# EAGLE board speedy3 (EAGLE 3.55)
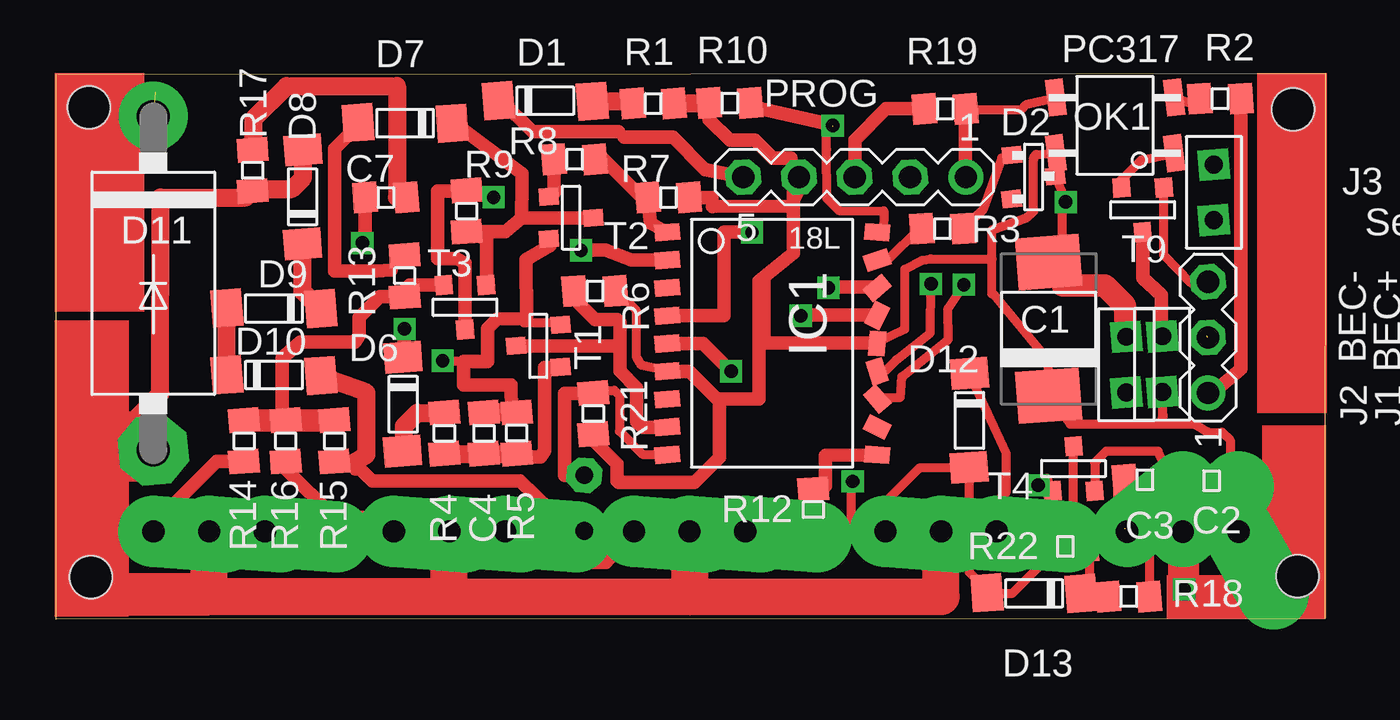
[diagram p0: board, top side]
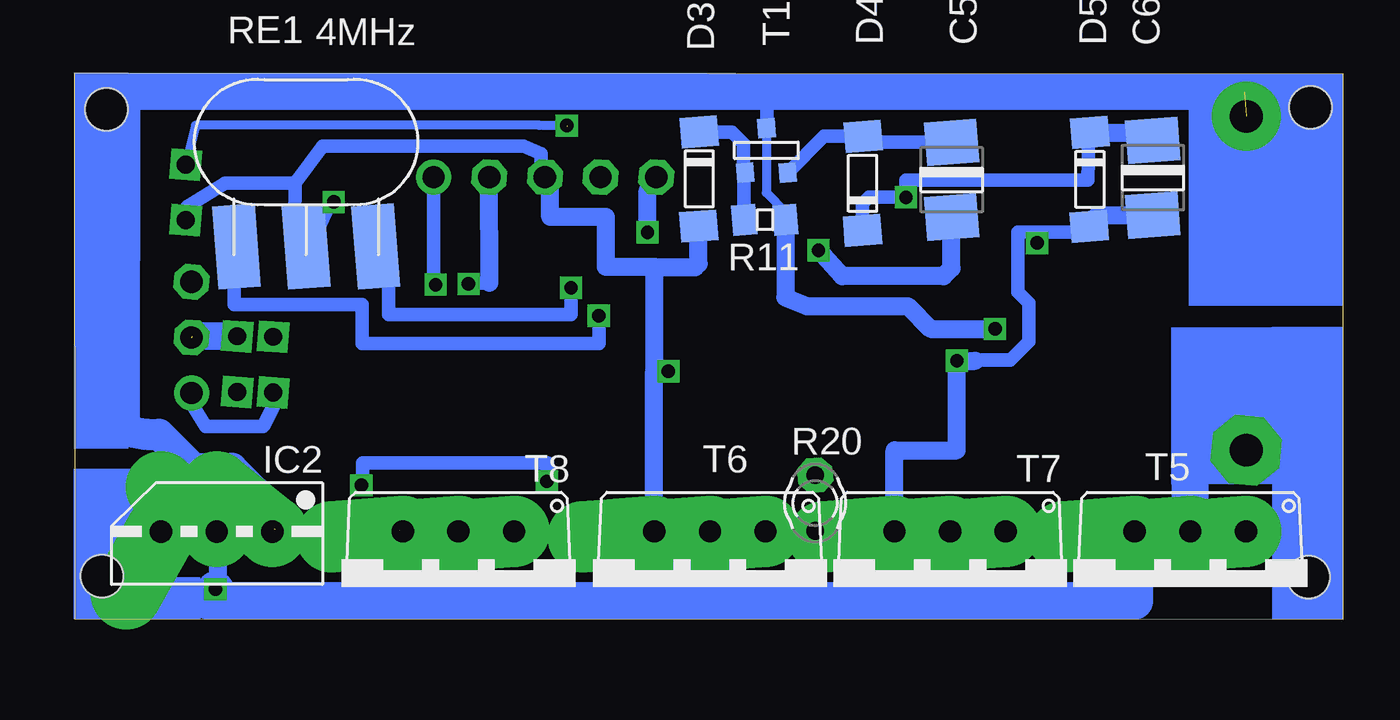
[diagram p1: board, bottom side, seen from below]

Size 57.92 x 24.93 mm. Coordinates in mm from the lower left corner, seen from the top.
Outline: 0,24.89 57.92,24.93 57.9,0.02 0,0 0,24.89
Copper layers used: Top, Bottom
Holes 1.93 mm at 1.5,23.37 1.58,1.92 56.64,1.97 56.45,23.28

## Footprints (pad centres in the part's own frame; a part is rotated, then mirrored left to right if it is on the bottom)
43 = smd 2.388 x 2.896 rotated 4.4:  3.048,0 | smd 2.388 x 2.896 rotated 4.3:  -3.048,0
05 = smd 1.092 x 1.397 rotated 4.4:  0.94,0 | smd 1.092 x 1.397 rotated 4.3:  -0.94,0
28 = smd 2.007 x 2.388 rotated 4.4:  1.702,0 | smd 2.007 x 2.388 rotated 4.3:  -1.702,0
D-80 = smd 1.397 x 1.702 rotated 4.4:  -2.388,0 | smd 1.397 x 1.702 rotated 4.3:  1.905,-0.025
T-23 = smd 0.787 x 0.889 rotated 6.7:  -1.24,-0.669 | smd 0.787 x 0.889 rotated 5.7:  0.754,-0.688 | smd 0.787 x 0.889 rotated 6.6:  -0.197,-2.662
201-15 = drill 1.499 pad 3.15 round:  -7.62,0 | drill 1.499 pad 3.15 octagon:  7.62,0
-18L = smd 0.762 x 1.143 rotated 4.3:  -5.08,-5.131;  5.08,4.445 | smd 0.762 x 1.143 rotated 4.4:  -3.81,-5.131 | smd 0.762 x 1.143 rotated 4.5:  -2.54,-5.131 | smd 0.762 x 1.143 rotated 4.6:  -1.27,-5.131 | smd 0.762 x 1.143 rotated 4.7:  0,-5.131;  1.27,-5.131 | smd 0.762 x 1.143 rotated 4.8:  2.54,-5.131 | smd 0.762 x 1.143 rotated 4.9:  3.81,-5.131 | smd 0.762 x 1.143 rotated 5:  5.08,-5.131 | smd 0.762 x 1.143 rotated 26.8:  3.81,4.445 | smd 0.762 x 1.143 rotated 49.3:  2.54,4.445 | smd 0.762 x 1.143 rotated 71.8:  1.27,4.445 | smd 0.762 x 1.143 rotated 94.3:  0,4.445 | smd 0.762 x 1.143 rotated 116.8:  -1.27,4.445 | smd 0.762 x 1.143 rotated 139.3:  -2.54,4.445 | smd 0.762 x 1.143 rotated 161.8:  -3.81,4.445 | smd 0.762 x 1.143 rotated 184.3:  -5.08,4.445
MXXS = drill 1.016 pad 3.251 offset:  -2.54,-2.54;  0,-2.54;  2.54,-2.54
N2 = drill 0.813 pad 1.397 square:  -1.27,0;  1.27,0
D4 = smd 0.813 x 1.676 rotated 97:  -1.27,-2.54;  1.27,-2.54;  1.27,2.857;  -1.27,2.857
05-1 = drill 1.016 pad 1.6 round:  -5.08,0 | drill 1.016 pad 1.6 octagon:  -2.54,0;  0,0;  2.54,0;  5.08,0
40 = drill 0.813 pad 1.6 octagon:  -1.27,0;  1.27,0
SONAT = smd 1.93 x 3.81 rotated 4.5:  3.175,-4.445 | smd 1.93 x 3.81 rotated 4.3:  -3.175,-4.445 | smd 1.93 x 3.81 rotated 4.4:  0,-4.445
03-1 = drill 1.016 pad 1.6 round:  -2.54,0 | drill 1.016 pad 1.6 octagon:  0,0;  2.54,0
T-23' = smd 0.787 x 0.889 rotated 4.4:  0.991,1.016 | smd 0.787 x 0.889 rotated 4.3:  -0.94,1.016 | smd 0.787 x 0.889 rotated 4.5:  0.025,-1.016
220V = drill 1.016 pad 3.251 offset:  -2.54,-2.54;  0,-2.54;  2.54,-2.54

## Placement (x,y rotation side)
C1  47u/10  [43]  45.29,13.25 90 top
C2  100n  [05]  52.72,6.33 0 top
C3  100n  [05]  49.69,6.37 180 top
C4  47n  [05]  19.52,8.5 90 top
C5  2æ2/25  [28]  17.88,20.07 270 bottom
C6  3u3/20  [28]  8.7,20.16 270 bottom
C7  22n  [05]  15.04,19.26 0 top
D1  LL4148  [D-80]  22.56,23.67 0 top
D2  LED-SMD  [T-23]  42.93,20.43 90 top
D3  15V  [D-80]  29.39,19.86 270 bottom
D4  LL4148  [D-80]  21.94,20.14 90 bottom
D5  ZDIO-15V  [D-80]  11.57,19.84 270 bottom
D6  ZDIO-5V6  [D-80]  15.83,9.58 270 top
D7  LL4148  [D-80]  15.68,22.64 180 top
D8  LL4148  [D-80]  11.24,19.52 90 top
D9  ZDIO-22V  [D-80]  9.7,14.18 180 top
D10  ZDIO-22V  [D-80]  10.18,11.15 0 top
D11  SB550  [201-15]  4.43,15.34 270 top
D12  ZD15  [D-80]  41.68,8.84 270 top
D13  LL4148  [D-80]  44.38,1.19 180 top
IC1  16F84SO  [-18L]  33.02,12.59 270 top
IC2  LM2940CT  [MXXS]  51.41,1.47 180 bottom
J1  BEC+  [N2]  50.47,11.65 90 top
J2  BEC-  [N2]  48.83,11.63 270 top
J3  Setup  [N2]  52.83,19.49 270 top
OK1  PC317  [D4]  48.47,22.55 90 top
PROG  MA05-1  [05-1]  36.43,20.19 180 top
R1  1k  [05]  27.25,23.54 180 top
R2  120  [05]  53.12,23.76 180 top
R3  470  [05]  40.45,17.83 180 top
R4  1k  [05]  17.71,8.5 90 top
R5  1k  [05]  21.02,8.5 270 top
R6  47k  [05]  24.58,14.99 0 top
R7  1k  [05]  27.94,19.26 0 top
R8  4k7  [05]  23.65,21 0 top
R9  47k  [05]  18.73,18.64 90 top
R10  1k  [05]  30.73,23.57 0 top
R11  10k  [05]  26.4,18.24 0 bottom
R12  47k  [05]  34.55,5 270 top
R13  470  [05]  15.91,15.67 270 top
R14  220  [05]  8.57,8.14 90 top
R15  220  [05]  12.7,8.14 90 top
R16  220  [05]  10.48,8.14 90 top
R17  47  [05]  8.97,20.49 270 top
R18  10k  [05]  48.94,1.04 0 top
R19  4k7  [05]  40.56,23.3 0 top
R20  NTC 10k  [40]  24.1,5.31 90 bottom
R21  4k7  [05]  24.51,9.39 270 top
R22  82k  [05]  46.06,3.33 180 top
RE1  4MHz  [SONAT]  47.33,21.47 0 bottom
REC  MA03-1  [03-1]  52.56,12.87 90 top
T1  BC817  [T-23']  22,12.51 270 top
T2  BC817  [T-23']  23.49,18.3 90 top
T3  BC817  [T-23']  18.63,14.24 0 top
T4  BC817  [T-23']  46.45,6.88 180 top
T5  IRF3205  [220V]  6.98,1.48 180 bottom
T6  IRF3205  [220V]  28.91,1.48 180 bottom
T7  IRF3205  [220V]  17.95,1.48 180 bottom
T8  IRF9540 o..  [220V]  40.38,1.48 180 bottom
T9  BC817  [T-23']  49.55,18.69 0 top
T10  BC817  [T-23']  26.3,21.41 180 bottom

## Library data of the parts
C1 C5 C6 D1 D3-D10 D12 D13 R11 R14 R19 R21 R22 T9 T10 = SMD
C2-C4 C7 R2 R15-R17 = DEMO
D2 J1-J3 OK1 = d-part
D11 = DIODE
IC1 = PIC
IC2 = V-REG
PROG REC = CON-LSTB
R1 R3-R10 R12 R13 R18 = DISCRETE
R20 = ptc-ntc
RE1 = hans
T1-T4 = NPN
T5-T8 = FET

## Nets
+15V: C6. D4. D5. R9. T3.
AKKU+: C3. D6. D11. D12. IC2. R11. R18. T8. T10.
GND: C1. C2. C3. C4. C6. C7. D2. D3. D5. IC1. IC2. J2. J3. PROG. R5. R19. R20. RE1. T1. T2. T4. T5. T6. T7.
N$1: IC1. RE1.
N$3: IC1. PROG.
N$4: C5. IC1.
N$5: REC. T9.
N$6: IC1. R3.
N$8: D6. R4.
N$9: D2. R3.
N$10: R8. T2.
N$11: C4. R4. R5. T1.
N$12: IC1. R6. T1.
N$13: IC1. R7. R8.
N$14: R13. R14. R15. R16. T3.
N$15: R12. T4.
N$16: IC1. R12.
N$18: D7. R9. T2. T3.
N$19: IC1. J3. R10.
N$20: D8. D11. R17. T5. T6. T7. T8.
N$21: D7. R13.
N$22: IC1. RE1.
N$23: J1. REC. T9.
N$24: D10. R15. T6.
N$25: OK1. T9.
N$26: D1. IC1. PROG.
N$27: C5. D4. T10.
N$28: D8. D9.
N$29: IC1. OK1. PROG. R19.
N$30: D3. R11. T10.
N$31: OK1. R2.
N$32: R16. T7.
N$33: IC1. R20. R21.
N$34: D1. R1.
N$35: D9. D10.
N$37: C7. R17.
N$38: R14. T5.
N$39: J2. R2. REC.
N$41: D13. R18. R22. T4.
N$43: D12. D13. R22. T8.
VCC: C1. C2. IC1. IC2. J1. OK1. PROG. R1. R6. R7. R10. R21.

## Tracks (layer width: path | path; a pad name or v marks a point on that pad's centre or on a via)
+15V  (via drill 0.61 pad 1.02)
  Top 0.406: 18.73,19.58 18.73,19.26 18.66,19.54 18.67,19.54 18.69,19.52 | 17.42,19.45 17.41,19.46 17.41,19.54 | v19.96,19.27 18.92,19.28 18.68,19.52 18.69,19.52 | 18.69,19.52 18.7,19.51
  Top 0.61: T3. 18.66,16.27 18.27,16.47 17.41,16.47 17.41,19.54 18.66,19.54
  Bottom 0.406: C6. 8.81,22.01 8.82,22 9.05,22.23 | 11.57,22.23 11.65,22.23 11.72,22.3 | v19.96,19.27 v19.96,19.28 19.93,19.31 19.97,19.35
  Bottom 0.61: 11.65,22.23 11.65,20.95 11.66,20.06 19.97,20.06 19.97,19.35 | v19.96,19.28 21.64,19.28 21.94,18.98 21.94,17.84 21.97,17.81 21.94,17.78 21.94,17.75
  Bottom 0.813: 11.65,22.23 9.05,22.23
AKKU+  (via drill 0.61 pad 1.02)  (3 unrouted)
  Top 0.406: 43.36,7.57 43.36,5.8 43.06,5.5 43.06,4.07 43.07,4.07 T8. | 43.36,7.57 | 43.36,7.57 41.68,11.23 | 48.83,3.85 48.83,3.95 48.84,3.96 49.88,2.92 49.88,1.04 | 48.82,3.96 48.9,4.04 | v48.78,3.96 48.82,3.96 | v48.77,3.95 48.81,3.95 48.82,3.96
  Top 0.61: v15.9,13.26 15.87,13.26 15.87,11.97 15.83,11.97 | 48.88,3.99 48.75,4.12 | 48.88,3.99 48.77,3.99 | 48.87,3.95 48.84,3.92 | 48.87,3.95 48.87,4.01 | 48.88,3.96 48.88,3.99 | 48.88,3.96 48.87,3.95 | 48.88,3.96 48.84,3.96 v48.78,3.96 v48.77,3.95 48.84,3.95
  Top 1.016: 48.75,4.12 48.75,6.37
  Bottom 0.406: 27.87,24.09 27.91,24.15 28.04,24.13 | 26.24,22.59 T10. 26.33,19.47 25.46,18.6 25.46,18.24 25.46,18.14 25.41,18.09 25.45,18.05 25.41,17.8 25.3,18.1 25.3,18.16 | 25.3,18.16 25.41,18.27 | 25.3,18.16 25.46,17.87 | 48.9,4.15 48.9,3.96 48.9,3.95 v48.77,3.95 | 48.85,4.06 48.79,4.12 48.75,4.12 | 43.06,4.06 48.85,4.06 | 48.85,4.06 48.93,3.98
  Bottom 0.61: 26.24,22.59 26.29,22.59 26.29,24.2 27.91,24.2 | 27.91,24.2 27.91,24.15 27.87,24.09 | 27.91,24.2 27.91,24.24
  Bottom 0.813: v15.9,13.26 18.84,13.26 19.88,14.3 24.48,14.3 25.46,14.7 25.46,17.87
  Bottom 1.422: 55.62,24.09 55.62,8.62 54.6,8.45 54.04,8.45 52.49,6.9 50.72,6.9 48.75,4.93 48.75,4.01 48.8,3.96 48.8,3.88 | 48.8,3.88 48.83,3.85 | v48.78,3.96 48.78,3.9 48.8,3.88
  Bottom 1.676: 4.52,24.06 27.87,24.09 55.62,24.09 55.64,24.09
GND  (via drill 0.61 pad 1.02)
  Top 0.406: 22.54,17.35 22.53,17.37 22.48,17.37 | v17.63,11.8 18.61,11.79 | 27.81,12.62 27.84,12.62 27.87,12.65 27.93,12.59 | 20.79,9.49 21.19,9.4 | 21.19,9.4 21.09,9.3 21.19,9.3 21.19,9.4 | 19.52,9.44 19.52,9.53 19.54,9.55 19.65,9.44 | 21.19,9.4 21.19,9.44 R5. | v13.97,17.18 14.1,17.69 | 45.91,15.96 45.29,16.3 45.89,15.27 45.9,18.52 v46.07,19.05 46.03,18.91 | J3. 52.82,18.37 52.86,18.33 | 21.46,13.73 21.46,13.67 21.34,13.55 21.35,13.54 23.01,13.54 23.02,13.54 | 18.6,10.7 18.61,10.69 | 18.6,11.78 18.61,11.77 18.61,11.79 | 23.02,13.54 23.05,13.58 | 23.02,13.54 23.02,13.45 | 18.61,11.79 18.61,11.69 18.62,11.68 18.72,11.78 | D2. 45.99,19.34 46,19.02 46.03,18.91 | 46.03,18.91 46.06,18.88 | 47.39,5.87 47.39,7.15 47.9,7.67 50.28,7.67 50.71,6.84 50.71,6.49 50.63,6.57 C3.
  Top 0.61: v30.8,11.32 29.53,12.59 27.93,12.59 | 22.54,17.35 22.54,17.07 21.44,16.43 21.46,13.73 20.13,13.72 19.68,13.27 19.68,11.78 18.72,11.78 | 20.79,9.49 20.77,10.69 18.61,10.69 | 14.1,17.69 C7. | R19. 37.87,23.3 36.45,21.88 v36.45,20.18 | 18.6,11.78 18.6,10.7 | 45.29,16.3 45.92,15.27 45.91,15.27 45.94,15.24
  Top 0.813: R5. 19.65,9.44
  Top 1.016: 48.83,12.9 48.77,14.32 47.85,15.24 45.94,15.24 | 51.37,6.36 51.38,6.46 51.41,4.01 | 51.37,6.36 C2. | 51.37,6.36 51.23,6.36 51.26,6.52 51.24,6.5 C3.
  Top 1.422: v51.47,1.37 51.41,4.01
  Bottom 0.406: T7. 20.95,2.43 20.64,0.84 20.5,1.16 | 31.44,3.7 T6. | 36.43,20.19 36.51,20.21 36.2,20.21 | v30.8,11.32 31.43,11.32 | 11.21,18.46 11.67,18 11.61,17.93 D5. 11.59,17.92 11.83,17.68 11.83,17.67 11.85,17.66 11.88,17.68 | 47.91,16.45 47.91,16.35 | 47.91,16.45 47.87,16.45 47.97,16.35 47.97,16.25 47.14,16.84 v46.07,19.05 | RE1. 47.91,16.93 47.91,16.45 | 14.32,17.72 14.28,17.68 | 29.57,16.08 29.41,16.23 | 31.59,15.97 31.48,16.08 31.48,16.07 | 31.48,16.07 31.51,16.04 | 31.43,16.08 31.46,16.08 31.48,16.07 | v13.97,17.18 13.96,17.58 13.97,17.58 13.98,17.65 14.2,17.43 14.32,17.72 | 14.32,17.72 14.31,17.73 | 14.84,17.68 14.35,17.68 14.32,17.72 | 52.75,18.83 52.84,18.66 | 51.34,1.26 51.97,1.07 51.99,1.09 v51.47,1.37 | 36.43,20.19 36.43,20.23 36.62,20.42 | 36.36,20.18 36.26,20.08 | 36.43,20.19 36.37,20.19 36.36,20.18 | 17.53,11.83 16.67,11.94 | 17.53,11.83 17.54,11.83 | 16.81,11.8 17.53,11.83 | 20.43,7.67 20.39,7.63 | 20.43,7.67 20.44,7.67 | 20.48,7.72 20.43,7.67 | 36.53,20.19 36.52,20.18 v36.45,20.18 36.36,20.18 | 36.43,20.19 36.53,20.19 | 36.53,20.19 36.55,20.21
  Bottom 0.61: 47.83,19.92 46.57,21.6 37.4,21.6 36.62,21.25 36.62,20.42 | 47.83,19.92 47.87,16.45 | 17.54,11.83 16.19,11.84 15.19,11.84 14.35,12.68 14.35,14.45 14.84,14.94 14.84,17.68 11.88,17.68 | 52.84,18.66 J3. | 47.83,19.92 51.02,19.92 52.75,18.83 | T7. | T7. | T7. 20.51,4.04
  Bottom 0.813: v30.8,11.32 31.45,11.32 31.45,5.29 31.46,4.1 T6. | T7. 20.48,7.72 17.64,7.71 v17.63,11.8 16.81,11.8 | 36.2,20.21 36.2,18.37 33.66,18.37 33.66,16.08 31.43,16.08 31.43,11.32 | 11.21,18.46 8.7,18.46 | 29.41,16.23 D3. | 31.48,16.08 29.57,16.08 | 51.34,1.26 51.34,3.83 | 20.51,4.04 24.1,4.04
  Bottom 1.676: 31.44,0.84 20.64,0.84 9.52,0.84 T5. | 31.44,0.84 31.44,3.7 | 31.44,0.84 51.79,0.84 v51.47,1.37 | 20.5,1.16 T7.
N$1  (via drill 0.61 pad 1.02)
  Top 0.406: v33.97,13.86 34,13.89
  Top 0.61: 34,13.89 37.39,13.89
  Bottom 0.61: v33.97,13.86 33.97,12.58 44.77,12.58 44.77,14.37 50.61,14.37 50.61,17.02 | 50.72,16.96 50.5,17.02 51.12,16.93
  Bottom 0.813: 50.61,17.02 50.5,17.02
N$3  (via drill 0.61 pad 1.02)
  Top 0.406: 37.39,11.35 37.85,11.35 38.34,11.84 39.88,13.07 v39.92,15.31
  Bottom 0.61: v39.92,15.31 38.96,15.36
  Bottom 0.813: 38.96,15.36 38.97,20.19
N$4  (via drill 0.61 pad 1.02)
  Top 0.406: 27.8,16.41 27.81,16.43
  Top 0.61: 27.8,16.41 26.25,16.41 25.07,16.85 v23.95,16.85
  Bottom 0.813: 17.88,18.37 17.88,16.03 18.24,15.67 22.87,15.67 v23.95,16.85
N$5
  Top 0.406: 50.54,19.7 50.54,16.63 51.78,15.36 52.57,15.36 | 52.57,15.36 52.56,15.37 REC. | 52.57,15.36 52.63,15.3
N$6
  Top 0.406: 37.79,16.43 37.9,16.43 37.94,16.39 39.38,17.83 39.5,17.83
  Top 0.61: 37.39,16.43 37.79,16.43
N$8
  Top 0.406: 17.58,9.43 17.59,9.44 17.71,9.44
  Top 0.61: 15.87,7.7 15.84,7.67 D6.
  Top 0.813: 15.87,7.7 15.87,8.82 16.48,9.43 17.58,9.43
N$9
  Top 0.406: 43.62,21.18 43.15,21.05 42.3,18.72 R3.
N$10
  Top 0.406: 22.48,19.3 22.56,19.3 22.71,19.45
  Top 0.61: R8. 22.71,19.45
N$11
  Top 0.406: 21.02,7.56 21.18,7.56 | 21.18,7.56 21.24,7.5 | C4. 19.52,7.53 19.49,7.5 19.44,7.55 19.44,7.57 | 22.93,11.49 23.02,11.52 | 21.18,7.56 21.18,7.24 21.17,7.42 | 19.44,7.57 19.46,7.59 | 19.43,7.56 19.44,7.57
  Top 0.61: 22.93,11.49 22.29,11.49 22.29,7.69 22.1,7.42 21.17,7.42
  Top 0.813: C4. 21.02,7.56 | R4. 19.43,7.56
N$12
  Top 0.406: 25.72,11.74 25.69,11.63 25.71,11.63 25.71,12.45 | 25.72,13.56 25.6,13.68 | 23.61,14.67 23.64,14.7 R6. | 27.81,8.81 27.53,8.81 27.47,8.75 | 25.71,12.45 25.74,11.61 | 25.71,12.45 25.71,12.48 25.7,12.5 25.69,12.48
  Top 0.61: 25.72,13.56 25.72,11.74 25.72,11.33 26.48,10.57 26.48,9.04 26.77,8.75 27.47,8.75 | 25.6,13.68 24.6,13.68 23.61,14.67 | 25.69,12.48 T1.
N$13
  Top 0.406: 27.94,17.67 27.94,17.7 27.81,17.7 | R7. 26.99,19.26 26.73,19.26 | 26.73,19.26 26.81,19.18 | 26.73,19.26 26.67,19.26 | 24.99,21 24.59,21
  Top 0.61: 27.81,17.7 27.11,18.08 26.99,19.26 | 26.73,19.26 24.99,21
N$14
  Top 0.406: 8.57,9.08 8.57,9.1 8.58,9.08 | 10.48,9.08 10.48,9.1 10.49,9.08 10.4,9.08 10.37,9.06 10.34,9.09 9.63,9.06 9.6,9.06 | 15.91,14.73 15.88,15.14 15.95,15.08 16.13,15.26
  Top 0.61: 16.13,15.26 17.69,15.26 | 15.91,14.73 14.78,14.73 13.83,13.78 13.83,12.96 13.65,12.67 11.16,12.67 10.31,11.93 10.31,9.08 10.34,9.05 | 10.34,9.05 10.38,9.01 | 10.34,9.09 10.34,9.05
  Top 1.016: 8.58,9.08 10.48,9.08 | 10.49,9.08 12.7,9.08
N$15  (via drill 0.61 pad 1.02)
  Top 0.406: 34.55,4.06 36.01,4.06 36.29,4.34 36.29,5.92 v36.35,6.3 | 45.46,5.87 45.41,5.97 45.21,6.45 44.78,6.11 v44.81,6.12
  Bottom 0.406: v36.35,6.3 36.31,6.3 | 44.76,6.3 44.67,6.3 v44.81,6.12
  Bottom 0.61: 36.31,6.3 36.31,7.14 44.76,7.14 44.76,6.3
N$16
  Top 0.406: 37.15,7.51 37.17,7.54 37.39,7.54 37.44,7.54 37.46,7.51 | R12. 35.11,6.09
  Top 0.61: 35.11,6.09 35.09,7.49 37.46,7.51
N$18
  Top 0.406: 24.55,18.3 24.74,18.33 T2. | R9. 19.37,17.35 19.63,17.36 | 19.63,15.4 19.52,15.23 19.62,15.26 | 18.17,22.65 18.07,22.65
  Top 0.61: R9. 20.5,17.7 21.24,18.32 | 21.24,18.32 24.55,18.3 | 19.63,15.4 19.63,17.36 | 21.24,18.32 21.25,19.9 21.25,20.33 18.17,22.65
N$19  (via drill 0.61 pad 1.02)  (1 unrouted)
  Top 0.406: 37.15,17.67 37.17,17.7 37.39,17.7 37.39,17.63 37.41,17.61 37.44,17.64 37.74,17.67 37.77,18.64 35.72,18.67 35.16,19.21 35.16,21.46 35.16,22.26 35.4,22.5 35.42,22.5 | 31.94,23.36 31.67,23.57
  Top 0.61: 35.42,22.5 35.17,22.63 31.94,23.36
  Bottom 0.406: v35.43,22.54 36.54,22.54 36.68,22.55 52.37,22.55 52.83,20.76
N$20
  Top 0.406: 28.94,1.03 29.84,1.16 | 17.94,1.04 18.41,1.16 | 8.97,19.59 9.02,19.65 9.02,19.55 | 8.97,19.59 8.97,19.55 | 8.97,19.59 8.63,19.26 8.66,19.26 8.67,19.25 | 9.02,19.55 8.97,19.5 | 9.02,19.55 9.12,19.65
  Top 0.61: D11. 3.44,8.97
  Top 0.813: 3.44,8.97 4.76,10.29 4.76,19.26 8.66,19.26 | D8. 11.27,20.15 10.77,19.65 9.12,19.65
  Top 1.676: 40.38,4.02 40.38,1.04 28.94,1.03 | 17.94,1.04 28.94,1.03 | 28.94,1.03 28.91,4.02 | 6.98,4.02 6.98,1.04 17.94,1.04 | 17.94,1.04 17.95,4.02
  Bottom 0.406: 6.98,4.02 7.3,3.7 | 4.76,8.15 D11.
  Bottom 1.676: 6.98,4.02 6.98,7.19 4.76,8.15
N$21
  Top 0.406: 13.82,22.6 13.78,22.64 D7. | R13. 15.91,16.59 15.29,15.98 15.29,15.94
  Top 0.61: 15.29,15.94 14.6,15.9 12.7,15.9 12.7,21.48 13.82,22.6
N$22  (via drill 0.61 pad 1.02)
  Top 0.406: v35.24,15.13 35.27,15.16
  Top 0.61: 35.27,15.16 37.39,15.16
  Bottom 0.61: v35.24,15.13 35.24,13.92 43.56,13.92 43.56,16.93 44.16,17.02
N$23  (1 unrouted)
  Top 0.61: T9. 49.58,15.58 50.42,14.8 50.42,13.25 50.49,13.18 J1.
  Bottom 1.27: J1. 52.51,12.93
N$24
  Top 0.406: 13.65,6.87 13.65,7.19
  Top 0.61: 12.19,11.07 12.22,11.3 D10. | 13.65,6.87 13.86,6.87 14.41,6.33 21.16,6.33 22.49,5.04 22.5,3.32 23.08,2.61 25.1,2.61 26.26,4.02 26.37,4.02 | 13.67,7.19 13.74,7.13 | 13.65,7.19 13.67,7.19 | R15. 13.66,7.21 13.67,7.19
  Top 0.813: 13.65,7.19 14.16,7.51 14.16,10.35 12.19,11.07
N$25
  Top 0.406: 51.01,21.28 49.52,20.97 48.58,20.03 48.63,19.55 48.59,19.96 | 48.59,19.96 48.6,19.57 | 48.61,19.7 48.59,19.96
N$26  (via drill 0.61 pad 1.02)
  Top 0.406: 27.81,13.89 27.88,13.89 27.92,13.85 27.93,13.86 | 25.92,22 25.66,22.26 | 20.28,23.71 20.24,23.67 20.17,23.67
  Top 0.61: v31.75,17.67 30.48,17.67 30.48,13.86 27.93,13.86 | PROG. 29.61,20.53 28.14,22 25.92,22 | 25.66,22.26 21.73,22.26 20.28,23.71
  Bottom 0.406: PROG. 31.75,20.53
  Bottom 0.813: v31.75,17.67 31.75,19.58 PROG.
N$27
  Bottom 0.61: C5. 22.01,21.77 22.01,22.04 D4. 23.69,22.04 25.36,20.38 | 25.36,20.38 25.39,20.35 | 25.36,20.38 25.36,20.39
N$28
  Top 0.406: 11.82,14.4 11.78,14.44 12.08,14.19
  Top 0.813: 11.24,17.13 11.24,14.97 11.78,14.44
N$29  (via drill 0.61 pad 1.02)
  Top 0.406: 41.5,23.3 41.71,23.3 41.75,23.26 44.03,23.26 44.28,23.51 45.61,23.82 | v41.42,15.28 40.7,14.2 40.71,12.78 38.59,11.07 38.52,10.13 37.34,10.13 37.39,10.08
  Top 0.61: 41.51,20.19 41.55,20.19 41.57,20.21 41.5,20.28 41.5,23.3
  Bottom 0.406: v41.42,15.28 41.51,15.2
  Bottom 0.61: 41.51,15.2 41.51,20.19
N$30
  Bottom 0.406: 27.34,20.33 27.29,20.38 27.29,20.39 27.29,20.34 27.3,20.33 27.37,20.4 | 27.34,20.33
  Bottom 0.61: R11. 27.34,20.33 | 29.39,22.25 27.91,22.25 27.37,21.71 27.37,20.4
N$31
  Top 0.406: 52.19,23.76 52.26,23.84 | 52.19,23.76 52.18,23.76 | 51.01,23.82 51.93,23.51 52.19,23.76
N$32
  Top 0.406: R16. 10.48,6.87
  Top 0.61: 15.41,4.02 15.24,4.65 12.7,4.65 10.48,6.87
N$33
  Top 0.406: 24.45,10.32 24.45,10.33 R21. | 27.81,7.54 26.76,7.54 25.7,8.6 25.7,10.23 25.48,10.45 24.51,10.45
  Top 0.61: R20. 23.19,6.58 23.19,10.32 24.45,10.32 | R21. 24.51,10.31 | 24.51,10.31 24.51,10.45 | 24.51,10.31 24.54,10.28
N$34
  Top 0.406: 26.31,23.54 26.24,23.54 26.14,23.65
  Top 0.813: D1. 26.14,23.65
N$35
  Top 0.406: 7.79,11.15 7.73,11.28
  Top 0.61: 7.73,11.28 7.73,11.34 7.79,11.4
  Top 0.813: 7.79,11.4 D9.
N$37
  Top 0.406: 15.56,19.26 15.98,19.26 | R17. 9.05,21.43 9.07,21.45 9.02,21.5
  Top 0.813: 15.56,19.26 15.56,24.34 10.51,24.34 9.02,22.85 9.02,21.5
N$38
  Top 0.61: 4.45,4.02 4.45,4.33 7.31,7.21 R14.
N$39
  Top 0.61: 52.56,10.33 52.83,10.38 54.05,11.43 54.06,11.83 R2.
  Bottom 0.61: J2. 48.77,9.83 49.28,8.8 51.92,8.8 52.82,10.28 52.56,10.33
N$41
  Top 0.406: 47.16,3.17 R22. | R22. | T4. 46.42,3.91 R22. | 48.03,1.04 | 48.03,1.04 R18. 47.16,1.04 47.16,3.17 | 46.77,1.19 48.03,1.19 48.03,1.04 | 47.16,3.17 47.16,3.19
N$43
  Top 0.406: 37.84,4.64 37.85,4.65 | 37.84,4.64 37.84,4.02 | 37.84,4.64 37.75,4.55 37.75,3.99 37.7,3.99 37.8,4.09 37.8,5.31 39.42,6.93 D12. 41.66,2.16 42.6,1.21 | 42.6,1.21 42.62,1.2 | 42.6,1.21 D13. 42.5,1.21 42.52,1.2 43.64,1.2 45.12,2.68 45.12,3.33
VCC
  Top 0.406: 33.89,20.19 33.75,20.18 | 33.89,20.19 34.29,20.21 33.6,18.86 | 33.89,20.19 33.96,20.54 33.96,20.43 33.95,20.42 33.95,20.63 33.52,21.06 | 33.66,20.21 33.89,20.19 | 33.89,20.19 33.97,20.21 | 33.66,16.72 32.38,15.76 32.38,12.91 32.41,12.62 | 27.9,11.32 27.87,11.35 27.81,11.35 27.81,11.36 26.72,11.59 26.48,11.98 26.48,14.09 25.58,14.99 25.52,14.99 | 37.39,12.62 37.4,12.62 | 37.4,12.62 37.43,12.59 | 29.57,23.54 29.67,23.45 R10. 29.79,22.81 | 29.18,6.3 29.2,6.32 29.14,6.26 | 30.28,10.02 30.25,9.99 30.19,10.05 30.16,10.05 | 37.4,12.62 38.73,13.25 38.72,15.98 39.52,16.4 39.9,16.45 42.71,16.45 | 24.51,8.45 24.51,8.19 | 25.6,6.33 25.67,6.26 | 45.5,9.84 C1. 45.26,11.84 42.76,14.85 42.68,14.85 42.68,16.45 42.71,16.45 | 45.5,9.84 45.98,9.3 | OK1. 44.72,21.22 44.67,21.17 44.6,20.97 44.6,18.62 44.29,18.34 42.72,17.79 42.71,17.79 42.71,16.45 | 45.5,9.84 45.93,9.34 46.26,8.91 50.41,8.91 | 50.41,8.91 50.46,8.92 51.93,8.92 52.58,8.54 53.21,8.54 53.57,8.18 53.57,6.4 53.66,6.31 | 50.41,8.91 50.52,9.29 50.5,9.31 50.47,10.38 | 53.66,6.31 53.73,6.24 | 53.66,6.31 53.66,6.33
  Top 0.61: 33.6,18.86 29.95,18.83 29.92,19.26 28.88,19.26 | 33.66,20.21 33.66,16.72 32.07,15.45 32.07,10.05 30.16,10.05 28.89,11.32 27.9,11.32 | 32.41,12.62 37.39,12.62 | 29.79,22.81 30.74,21.87 31.9,21.87 32.71,21.06 33.52,21.06 | 29.2,6.32 30.28,7.4 30.28,10.02 | IC2. 54.03,3.92 | IC2. | 53.76,4.19 IC2. | 24.51,8.19 25.6,7.1 25.6,6.33 | 25.67,6.26 29.14,6.26
  Top 0.813: 29.57,23.54 R1.
  Top 1.016: 53.66,6.33 53.76,4.19
(copper drawn outside any net)
  shapes: Bottom area x6, Top area x7

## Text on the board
tNames: Sig. | +5V | Gnd
Document: Motor+ | Akku+ | Motor- | Akku-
